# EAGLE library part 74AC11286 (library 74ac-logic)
9-bit PARITY GENERATOR/CHECKER, bus driver
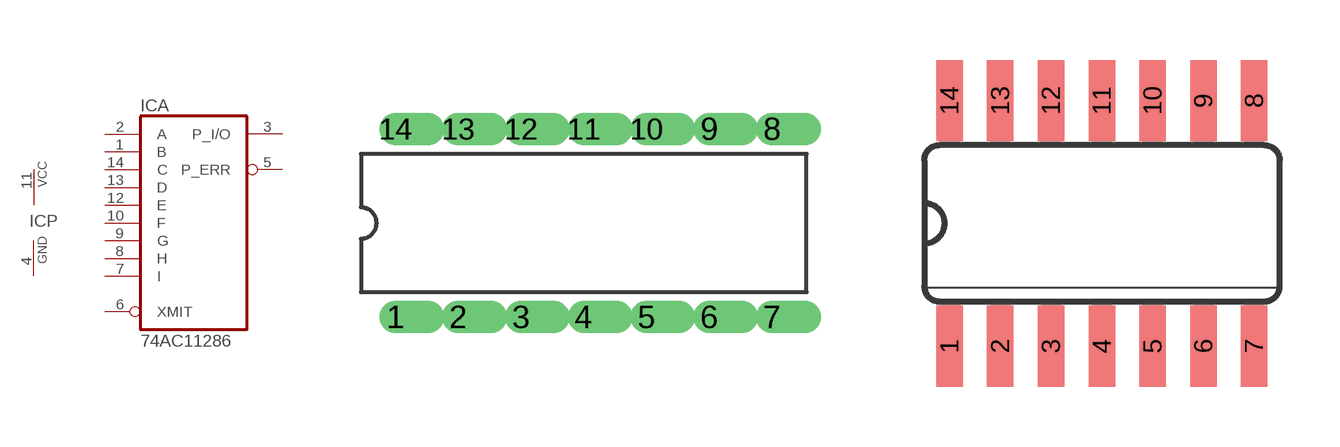
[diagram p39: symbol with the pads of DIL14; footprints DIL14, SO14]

Designator prefix IC; gates A=7411286 P=PWRN

## 74AC11286  [DIL14]
1  A:B  in
2  A:A  in
3  A:P_I/O
4  P:GND  pwr
5  A:P_ERR  out
6  A:XMIT  in
7  A:I  in
8  A:H  in
9  A:G  in
10  A:F  in
11  P:VCC  pwr
12  A:E  in
13  A:D  in
14  A:C  in

## 74AC11286D  [SO14]
Pads as for DIL14

## Footprint DIL14 (pad centres in mm)
Dual In Line
drill 0.813 offset: 1 -7.62,-3.81; 2 -5.08,-3.81; 3 -2.54,-3.81; 4 0,-3.81; 5 2.54,-3.81; 6 5.08,-3.81; 7 7.62,-3.81; 8 7.62,3.81; 9 5.08,3.81; 10 2.54,3.81; 11 0,3.81; 12 -2.54,3.81; 13 -5.08,3.81; 14 -7.62,3.81

## Footprint SO14 (pad centres in mm)
Small Outline package 150 mil
smd 0.66 x 2.032: 1 -3.81,-3.073; 2 -2.54,-3.073; 3 -1.27,-3.073; 4 0,-3.073; 5 1.27,-3.073; 6 2.54,-3.073; 7 3.81,-3.073; 8 3.81,3.073; 9 2.54,3.073; 10 1.27,3.073; 11 0,3.073; 12 -1.27,3.073; 13 -2.54,3.073; 14 -3.81,3.073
